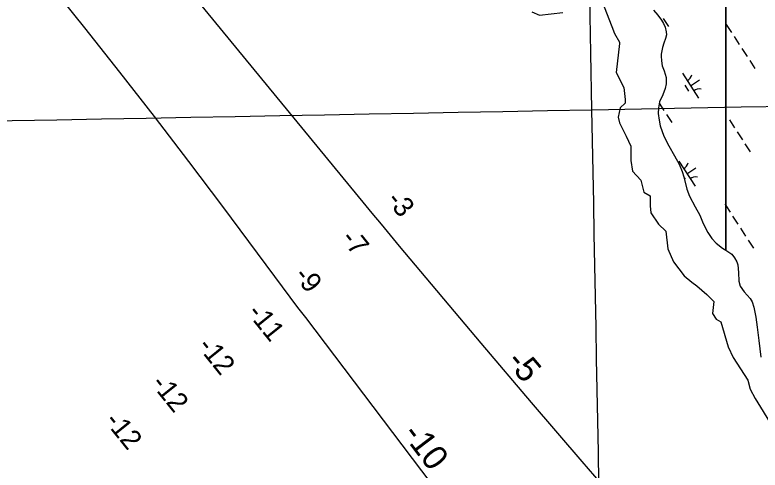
# Model space of a CAD drawing. Extents: x 3953924 to 3974542, y 193747 to 216192.
# Drawn here: x 3966966 to 3968214, y 199804 to 200567 of the extents above; entities that cross this region are included whole.
import ezdxf

# ---------------------------------------------------------------- set-up
doc = ezdxf.new("R2010")
doc.units = 0
for name, color, linetype in [('V-GRID-MAJR', 7, 'Continuous'), ('V-RIVR-EDGE', 7, 'Continuous'), ('V-RIVR-RANG', 7, 'Continuous'), ('V-TOPO-MINR', 7, 'Continuous'), ('V-TOPO-MINR-IDEN', 7, 'Continuous'), ('V-WETL-SWMP', 7, 'Continuous')]:
    doc.layers.add(name, color=color, linetype=linetype)

msp = doc.modelspace()

# ---------------------------------------------------------------- linework, layer by layer
at = {"layer": 'V-GRID-MAJR'}
for points in [[(3967994.9, 197070.8), (3967932.3, 200408.2), (3967818.6, 206468.2), (3967751, 210066.7)], [(3963152.5, 200318.9), (3967932.3, 200408.2), (3973258, 200508.6), (3973424, 200511.7)]]:
    msp.add_spline(points, degree=3, dxfattribs=at)
at = {"layer": 'V-RIVR-EDGE'}
for points in [[(3967831.4, 200572.6), (3967844.5, 200566.7), (3967883.7, 200571.4)], [(3967952.5, 200580.9), (3967965.6, 200547.7), (3967970.3, 200535.8), (3967978.6, 200521.6), (3967978.6, 200519.2), (3967972.7, 200470.5), (3967985.8, 200445.6), (3967988.1, 200425.4), (3967988.1, 200419.5), (3967979.8, 200411.2), (3967976.3, 200395.7), (3967978.6, 200386.2), (3967989.3, 200363.7), (3967997.6, 200347.1), (3967997.6, 200323.3), (3968000, 200305.5), (3968014.2, 200290.1), (3968019, 200269.9), (3968029.7, 200264), (3968029.7, 200247.3), (3968030.9, 200235.5), (3968043.9, 200216.5), (3968055.8, 200204.6), (3968059.4, 200174.9), (3968068.9, 200153.5), (3968086.7, 200129.8), (3968099.7, 200119.1), (3968108, 200113.2), (3968124.7, 200098.9), (3968136.5, 200087.1), (3968134.2, 200066.9), (3968140.1, 200057.4), (3968148.4, 200052.6), (3968160.3, 200011.1), (3968168.6, 199993.3), (3968193.5, 199955.3), (3968197.1, 199939.8), (3968205.4, 199924.4), (3968233.9, 199878.1)]]:
    msp.add_lwpolyline(points, dxfattribs=at)
at = {"layer": 'V-TOPO-MINR'}
for points in [[(3968162.6, 199537.2), (3968121.1, 199583.5), (3968086.5, 199622.8), (3968000.8, 199720.6), (3967915.6, 199818.9), (3967831, 199917.8), (3967746.9, 200017.1), (3967610.1, 200179.9), (3967594.8, 200198.2), (3967579.6, 200216.4), (3967564.4, 200234.8), (3967549.3, 200253.1), (3967127.4, 200767.1)], [(3967792.9, 199610.4), (3967452.8, 200059.9), (3967439.8, 200077), (3967426.9, 200094.2), (3967414, 200111.4), (3967401.2, 200128.6), (3967313.8, 200245.9), (3967256.9, 200321.5), (3967199.5, 200396.7), (3967141.3, 200471.3), (3967082.6, 200545.4), (3966965.7, 200691.7)]]:
    msp.add_lwpolyline(points, dxfattribs=at)
at = {"layer": 'V-WETL-SWMP'}
for p, q in [((3968156.3, 204867.5), (3968156.3, 200173.1)), ((3968156.3, 200173.1), (3968156.3, 204867.5)), ((3968035.6, 200575.4), (3968042.7, 200566.5)), ((3968042.7, 200566.5), (3968048.6, 200558.4)), ((3968048.6, 200558.4), (3968052.3, 200553)), ((3968051.6, 200561.2), (3968060.4, 200547.8)), ((3968052.3, 200553), (3968054.9, 200546.4)), ((3968054.9, 200546.4), (3968056.6, 200538.8)), ((3968157.3, 200551.2), (3968166, 200537.8)), ((3968056.9, 200533.8), (3968055.2, 200527.4)), ((3968056.6, 200538.8), (3968056.9, 200533.8)), ((3968055.2, 200527.4), (3968052.4, 200519.8)), ((3968170.4, 200531.1), (3968179.1, 200517.7)), ((3968050.4, 200512.6), (3968048.3, 200501.2)), ((3968052.4, 200519.8), (3968050.4, 200512.6)), ((3968183.5, 200511), (3968192.2, 200497.6)), ((3968048.3, 200501.2), (3968048.2, 200497.8)), ((3968048.2, 200497.8), (3968048.8, 200490.1)), ((3968048.8, 200490.1), (3968049.8, 200482.1)), ((3968196.6, 200490.9), (3968205.3, 200477.5)), ((3968049.8, 200482.1), (3968053.1, 200473.7)), ((3968053.1, 200473.7), (3968056.3, 200462.5)), ((3968056.3, 200462.5), (3968056.4, 200451.5)), ((3968083.7, 200469.4), (3968111, 200427.5)), ((3968097.3, 200448.5), (3968112.4, 200458.3)), ((3968056.4, 200451.5), (3968055.1, 200443.9)), ((3968087.6, 200449.3), (3968094.1, 200439.2)), ((3968051.1, 200433.3), (3968045.2, 200421.6)), ((3968055.1, 200443.9), (3968051.1, 200433.3)), ((3968045.2, 200421.6), (3968043.8, 200411.3)), ((3968043.8, 200411.3), (3968043.3, 200402.2)), ((3968044.9, 200419.1), (3968052.8, 200406.9)), ((3968043.3, 200402.2), (3968044.6, 200390.7)), ((3968057.2, 200400.2), (3968065.9, 200386.8)), ((3968044.6, 200390.7), (3968046.7, 200381.2)), ((3968162.4, 200391.1), (3968171.1, 200377.7)), ((3968046.7, 200381.2), (3968052.8, 200363.9)), ((3968175.5, 200371), (3968184.2, 200357.6)), ((3968052.8, 200363.9), (3968060.9, 200347.7)), ((3968060.9, 200347.7), (3968070.5, 200331.1)), ((3968188.6, 200350.9), (3968197.3, 200337.5)), ((3968070.5, 200331.1), (3968078.2, 200316.9)), ((3968077.7, 200322.1), (3968105, 200280.2)), ((3968078.2, 200316.9), (3968083.3, 200305)), ((3968091.4, 200301.1), (3968106.4, 200310.9)), ((3968083.3, 200305), (3968086.2, 200295.8)), ((3968086.2, 200295.8), (3968091.1, 200275.1)), ((3968086.5, 200294.4), (3968088.2, 200291.9)), ((3968091.1, 200275.1), (3968095.9, 200263.6)), ((3968095.9, 200263.6), (3968105.4, 200245.5)), ((3968105.4, 200245.5), (3968113.2, 200231.6)), ((3968154.8, 200250.2), (3968156.3, 200247.9)), ((3968156.3, 200247.9), (3968163.5, 200236.8)), ((3968113.2, 200231.6), (3968118.6, 200217.8)), ((3968167.9, 200230.1), (3968176.6, 200216.7)), ((3968118.6, 200217.8), (3968126.3, 200202.4)), ((3968181, 200210), (3968189.7, 200196.5)), ((3968126.3, 200202.4), (3968133, 200192.3)), ((3968133, 200192.3), (3968140.5, 200184.9)), ((3968140.5, 200184.9), (3968151, 200176.3)), ((3968194.1, 200189.8), (3968202.8, 200176.4)), ((3968151, 200176.3), (3968156.3, 200173.1)), ((3968156.3, 200173.1), (3968160, 200170.8)), ((3968160, 200170.8), (3968166.4, 200166.1)), ((3968166.4, 200166.1), (3968171.2, 200160.3)), ((3968171.2, 200160.3), (3968174.9, 200153.4)), ((3968174.9, 200153.4), (3968176.4, 200148.4)), ((3968176.4, 200148.4), (3968177.6, 200135.4)), ((3968177.6, 200135.4), (3968178.1, 200120.9)), ((3968178.1, 200120.9), (3968180.6, 200112.5)), ((3968180.6, 200112.5), (3968187.3, 200103.2)), ((3968187.3, 200103.2), (3968197, 200092)), ((3968197, 200092), (3968200.7, 200086.6)), ((3968200.7, 200086.6), (3968203.6, 200077.4)), ((3968203.6, 200077.4), (3968206.7, 200060.9)), ((3968206.7, 200060.9), (3968209, 200043.7)), ((3968209, 200043.7), (3968211.6, 200021.6)), ((3968211.6, 200021.6), (3968214.9, 199993.7))]:
    msp.add_line(p, q, dxfattribs=at)
for centre, start, end in [((3968082.5, 200471.8), 302.2901, 343.8338), ((3968112.6, 200425.5), 82.2901, 123.8337), ((3968076.5, 200324.4), 302.2901, 343.8338), ((3968106.6, 200278.1), 82.2901, 123.8337)]:
    msp.add_arc(centre, 17.6, start, end, dxfattribs=at)

# ---------------------------------------------------------------- texts
at = {"layer": 'V-RIVR-RANG'}
for s, p in [('-3', (3967586.7, 200256.5)), ('-7', (3967510.4, 200191.7)), ('-9', (3967431.9, 200129.7)), ('-11', (3967353.5, 200067.7)), ('-12', (3967270.4, 200011.4)), ('-12', (3967192.5, 199948.8)), ('-12', (3967114.8, 199886.2))]:
    msp.add_text(s, height=33.5, rotation=308.817, dxfattribs=at).set_placement(p)
at = {"layer": 'V-TOPO-MINR-IDEN'}
for s, rotation, p in [('-5', 310.2542, (3967787.3, 199985.5)), ('-10', 307.1136, (3967613.6, 199864.5))]:
    msp.add_text(s, height=41.5, rotation=rotation, dxfattribs=at).set_placement(p)

doc.saveas('drawing.dxf')
